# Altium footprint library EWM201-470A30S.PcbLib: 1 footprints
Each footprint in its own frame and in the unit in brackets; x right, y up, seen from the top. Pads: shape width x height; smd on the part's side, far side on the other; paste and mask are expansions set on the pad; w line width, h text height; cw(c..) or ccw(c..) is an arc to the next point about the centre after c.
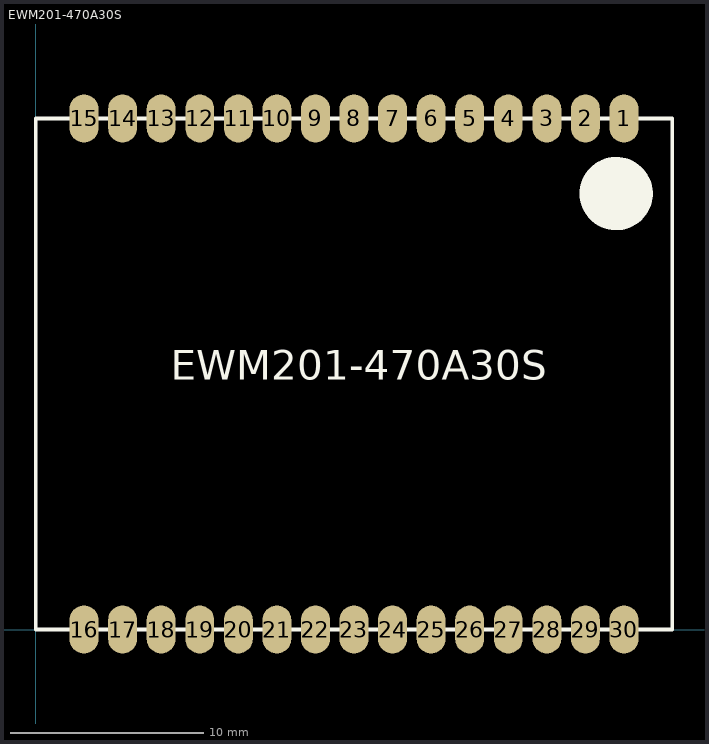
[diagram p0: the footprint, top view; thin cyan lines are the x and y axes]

## EWM201-470A30S [mm]
pads (30):
  oval 1.5x2.5 smd: 1(30.5,26.5) 2(28.5,26.5) 3(26.5,26.5) 4(24.5,26.5) 5(22.5,26.5) 6(20.5,26.5) 7(18.5,26.5) 8(16.5,26.5) 9(14.5,26.5) 10(12.5,26.5) 11(10.5,26.5) 12(8.5,26.5) 13(6.5,26.5) 14(4.5,26.5) 15(2.5,26.5) 16(2.5,0) 17(4.5,0) 18(6.5,0) 19(8.5,0) 20(10.5,0) 21(12.5,0) 22(14.5,0) 23(16.5,0) 24(18.5,0) 25(20.5,0) 26(22.5,0) 27(24.5,0) 28(26.5,0) 29(28.5,0) 30(30.5,0)
Top Overlay:
  circle w2: c30.099,22.606 r0.898
  lines w0.2: 0,0 0,26.5 33,26.5 33,0 0,0
  text "EWM201-470A30S" at 6.985,12.954 h1.52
